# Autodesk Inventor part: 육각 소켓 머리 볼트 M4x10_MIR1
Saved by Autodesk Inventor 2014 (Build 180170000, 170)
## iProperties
Created: 2024-05
Part Number: 육각 소켓 머리 볼트 M4x10_MIR1
Material: 일반
Document SubType Name: Modeling
Designer: dg
Density: 1 g/cm^3
Appearance: 기본값
Author: dg
Author: jhkim
Description: 6각머리 태핑 나사
Creation Date: 2024-05-07
Sending System: Autodesk Inventor 2025
Preprocessor: ST-DEVELOPER v20
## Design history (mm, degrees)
derived "육각 소켓 머리 볼트 M4x10.ipt"
feature "Solid1::육각 소켓 머리 볼트 M4x10.ipt" dims "d0" = 10
tag "피쳐 태그1"
node "솔리드1"
